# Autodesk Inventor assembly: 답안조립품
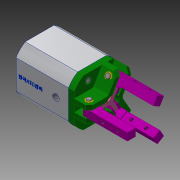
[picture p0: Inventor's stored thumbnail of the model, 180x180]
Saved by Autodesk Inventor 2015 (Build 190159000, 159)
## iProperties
Created: 2020-02
Part Number: 답안조립품
Document SubType Name: Assembly
Designer: LINEART-SSD.D4.16.05
Author: LINEART-SSD.D4.16.05
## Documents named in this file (13)
- C:\Users\LINEART-SSD.D4.16.05\Desktop\700206V1016\답안조립품.iam
- C:\Users\LINEART-SSD.D4.16.05\Desktop\700206V1016\본체.ipt
- C:\Users\LINEART-SSD.D4.16.05\Desktop\700206V1016\본체헤드.ipt
- C:\Users\LINEART-SSD.D4.16.05\Desktop\700206V1016\볼트 M4.ipt
- C:\Users\LINEART-SSD.D4.16.05\Desktop\700206V1016\피스톤.ipt
- C:\Users\LINEART-SSD.D4.16.05\Desktop\700206V1016\로드.ipt
- C:\Users\LINEART-SSD.D4.16.05\Desktop\700206V1016\핑거.ipt
- C:\Users\LINEART-SSD.D4.16.05\Desktop\700206V1016\O-RING 34x40.ipt
- C:\Users\LINEART-SSD.D4.16.05\Desktop\700206V1016\O-RING 12x16.ipt
- C:\Users\LINEART-SSD.D4.16.05\Desktop\700206V1016\핀 B.ipt
- C:\Users\LINEART-SSD.D4.16.05\Desktop\700206V1016\핀 A.ipt
- C:\Users\LINEART-SSD.D4.16.05\Desktop\700206V1016\E링.ipt
- C:\Users\LINEART-SSD.D4.16.05\Desktop\700206V1016\O-RING 18x22.ipt
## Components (20 placed, 8 different names)
1. 피스톤:1
2. O-RING 34x40:1
3. O-RING 12x16:1
4. 핑거:1 — 플러쉬:1
5. 핑거:2 — 플러쉬:2
6. 핑거:3 — 플러쉬:3
7. 핀 B:1 — 플러쉬:1
8. 핀 A:1
9. E링:1
10. E링:2
11. 핀 B:2 — 플러쉬:2
12. 핀 A:2
13. E링:3
14. E링:4
15. 핀 B:3 — 플러쉬:3
16. 핀 A:3
17. E링:5
18. E링:6
19. O-RING 18x22:1
20. O-RING 34x40:2
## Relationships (3: Flush 3)
- 플러쉬:1 [Flush]: 핑거:1 ↔ 핀 B:1
- 플러쉬:2 [Flush]: 핑거:2 ↔ 핀 B:2
- 플러쉬:3 [Flush]: 핑거:3 ↔ 핀 B:3
